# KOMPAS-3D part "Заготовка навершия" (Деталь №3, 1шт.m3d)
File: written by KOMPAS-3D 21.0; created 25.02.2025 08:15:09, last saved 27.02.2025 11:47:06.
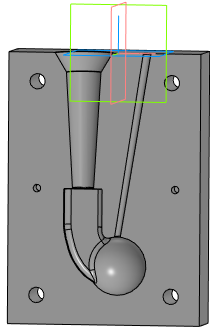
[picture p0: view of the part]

Document properties: Автор: User; Полное имя файла: C:\Users\Цыба.НГ\Downloads\Деталь №3, 1шт.m3d

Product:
- Part/product: Заготовка навершия
    Масса: 3.099981
- Part/product: Заготовка навершия  | designation 01
    Масса: 3.099981

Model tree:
1. Эскиз:1
2. Элемент выдавливания:1
     Расстояние 2 = 140
3. Вычесть компоненты:1
4. Скругление:1  (with: Вычесть компоненты:1)
     Радиус = 0.5
5. Эскиз:2  (with: Элемент выдавливания:1)
6. Элемент выдавливания:2
     Расстояние 2 = 100
7. Эскиз:3  (with: Элемент выдавливания:2)
8. Элемент выдавливания:3
9. Эскиз:4  (with: Элемент выдавливания:2)
10. Элемент выдавливания:4
     Расстояние 2 = 10

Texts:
  Точка начала. Х
  Точка начала. Y
  Точка начала. Z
